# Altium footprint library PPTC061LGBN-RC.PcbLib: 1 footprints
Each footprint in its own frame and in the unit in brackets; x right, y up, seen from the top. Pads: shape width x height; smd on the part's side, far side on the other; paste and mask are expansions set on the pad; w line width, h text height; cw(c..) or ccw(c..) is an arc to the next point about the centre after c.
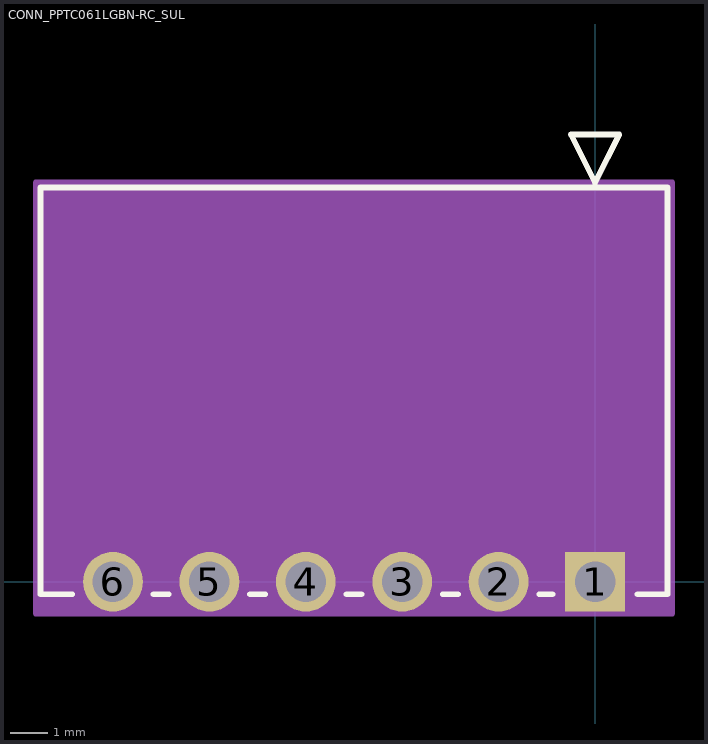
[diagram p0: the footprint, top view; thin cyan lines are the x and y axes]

## CONN_PPTC061LGBN-RC_SUL [mil]
pads (6):
  rect 62x62 hole 42 paste-31 mask+0: 1(0,0)
  round 62 hole 42 paste-31 mask+0: 2(-100,0) 3(-200,0) 4(-300,0) 5(-400,0) 6(-500,0)
Top Overlay:
  lines w6: -542.14,-13 -575,-13 -575,409 75,409 75,-13 44.1,-13 ; -457.86,-13 -442.14,-13 ; -357.86,-13 -342.14,-13 ; -257.86,-13 -242.14,-13 ; -157.86,-13 -142.14,-13 ; -57.86,-13 -44.1,-13 ; -25,464 0,414 25,464 -25,464
  text ".Designator" at -387.5,-25 h50
Mechanical 13:
  lines w1: -570,-8 70,-8 70,404 -570,404 -570,-8 ; -25,464 0,414 25,464 -25,464
  text ".Designator" at -387.5,-25 h50
Mechanical 15:
  region: 80,414 -580,414 -580,-33 80,-33
  lines w6: -580,-33 -580,414 80,414 80,-33 -580,-33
